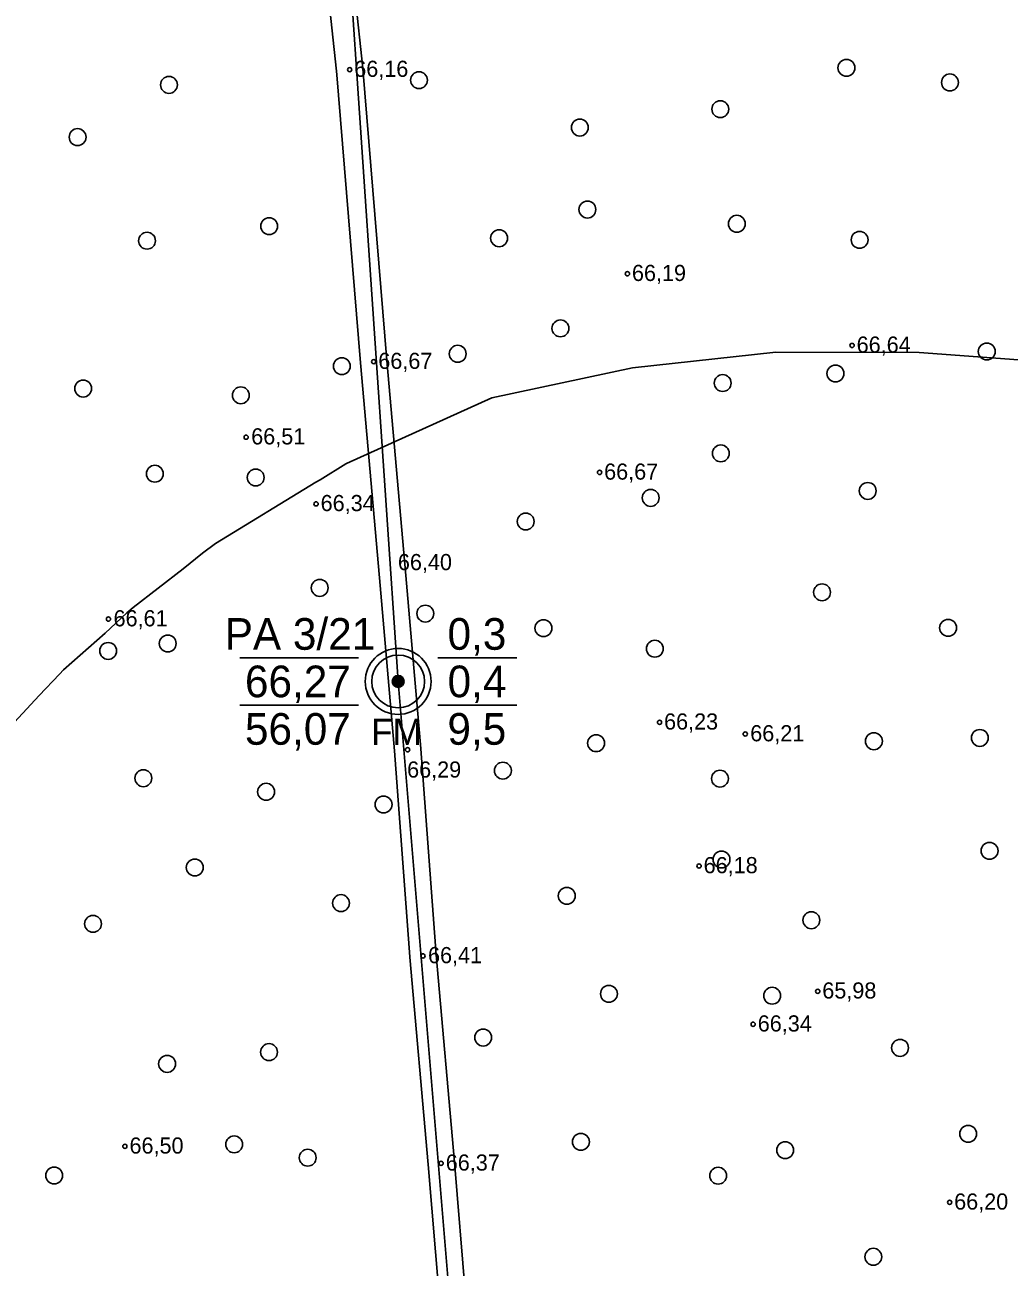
# Model space of a CAD drawing. Extents: x 532503 to 539665, y 6557663 to 6561526.
# Drawn here: x 534640.9 to 534790.2, y 6559799.2 to 6559987.5 of the extents above; entities that cross this region are included whole.
import ezdxf

# ---------------------------------------------------------------- set-up
doc = ezdxf.new("R2010")
doc.units = 0
for name, color, linetype in [('GEOLPUNKT', 7, 'Continuous'), ('HALJASTUS', 7, 'Continuous'), ('KORGUS-EH2000', 7, 'Continuous'), ('Lamami horisontaal_EH2000', 7, 'Continuous'), ('Lõige', 7, 'Continuous'), ('Proovid', 7, 'Continuous'), ('TEE', 7, 'Continuous')]:
    doc.layers.add(name, color=color, linetype=linetype)

# ---------------------------------------------------------------- blocks, each defined once
blk = doc.blocks.new('METS')
at = {"layer": 'HALJASTUS'}
blk.add_circle((0, 0), 0.8, dxfattribs=at)

msp = doc.modelspace()

# ---------------------------------------------------------------- linework, layer by layer
at = {"layer": 'GEOLPUNKT'}
for p, q in [((534673.52, 6559891.58), (534691.52, 6559891.58)), ((534703.52, 6559891.58), (534715.52, 6559891.58)), ((534673.52, 6559884.38), (534691.52, 6559884.38)), ((534703.52, 6559884.38), (534715.52, 6559884.38))]:
    msp.add_line(p, q, dxfattribs=at)
for radius in [5, 4, 0.9, 0.801, 0.7, 0.6, 0.5, 0.4, 0.3, 0.2, 0.1]:
    msp.add_circle((534697.52, 6559887.98), radius, dxfattribs=at)
at = {"layer": 'KORGUS-EH2000'}
for centre in [(534690.17, 6559980.74), (534732.29, 6559949.79), (534766.37, 6559938.92), (534693.81, 6559936.46), (534674.46, 6559925.01), (534728.07, 6559919.67), (534685.07, 6559914.9), (534653.58, 6559897.43), (534737.16, 6559881.78), (534750.16, 6559880), (534698.95, 6559877.62), (534743.16, 6559860), (534701.29, 6559846.36), (534761.16, 6559841), (534751.36, 6559836), (534656.07, 6559817.49), (534704.04, 6559814.91), (534781.16, 6559809)]:
    msp.add_circle(centre, 0.32, dxfattribs=at)
at = {"layer": 'Lamami horisontaal_EH2000'}
msp.add_lwpolyline([(534638.05, 6559880.42), (534643.05, 6559885.87), (534646.13, 6559889.1), (534646.78, 6559889.75), (534653.09, 6559895.32), (534656.36, 6559898.37), (534657.32, 6559899.2), (534664.9, 6559905.04), (534667.86, 6559907.45), (534669.84, 6559908.91), (534685.03, 6559918.18), (534685.67, 6559918.53), (534689.59, 6559920.99), (534689.7, 6559921.04), (534711.75, 6559930.99), (534733.06, 6559935.52), (534754.79, 6559937.88), (534776.53, 6559937.84), (534794.34, 6559936.54)], dxfattribs=at)
at = {"layer": 'Lõige'}
msp.add_lwpolyline([(534686.42, 6560054.5), (534688.17, 6560025.47), (534697.52, 6559887.98), (534707.91, 6559763.06), (534733.5, 6559485.14), (534735.54, 6559463.02)], dxfattribs=at)
at = {"layer": 'TEE'}
for p, q in [((534688.18, 6559980.53), (534685.22, 6560007.91)), ((534692.15, 6559980.96), (534689.2, 6560008.33)), ((534691.82, 6559936.29), (534688.17, 6559980.58)), ((534695.81, 6559936.62), (534692.16, 6559980.91)), ((534694.71, 6559903.7), (534691.82, 6559936.28)), ((534698.7, 6559904.05), (534695.81, 6559936.63)), ((534698.7, 6559904.04), (534700.94, 6559877.79)), ((534694.71, 6559903.7), (534696.95, 6559877.45)), ((534703.28, 6559846.51), (534700.94, 6559877.77)), ((534699.29, 6559846.21), (534696.95, 6559877.47)), ((534702.05, 6559814.74), (534699.29, 6559846.18)), ((534706.04, 6559815.09), (534703.28, 6559846.53)), ((534704.86, 6559781.73), (534702.05, 6559814.74)), ((534708.84, 6559782.07), (534706.04, 6559815.08))]:
    msp.add_line(p, q, dxfattribs=at)

# ---------------------------------------------------------------- block references
at = {"layer": 'HALJASTUS', "xscale": 1.6, "yscale": 1.6000000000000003}
for p in [(534765.51, 6559981.01), (534662.76, 6559978.42), (534700.68, 6559979.14), (534781.21, 6559978.8), (534746.38, 6559974.74), (534648.9, 6559970.51), (534725.07, 6559971.95), (534726.22, 6559959.52), (534748.89, 6559957.37), (534677.95, 6559957), (534659.43, 6559954.8), (534712.83, 6559955.17), (534767.51, 6559954.94), (534722.13, 6559941.51), (534706.55, 6559937.66), (534786.79, 6559938.01), (534688.97, 6559935.78), (534763.84, 6559934.66), (534746.74, 6559933.22), (534649.74, 6559932.38), (534673.65, 6559931.36), (534746.46, 6559922.56), (534660.62, 6559919.47), (534675.91, 6559918.9), (534768.74, 6559916.86), (534735.82, 6559915.8), (534716.86, 6559912.22), (534685.62, 6559902.16), (534761.81, 6559901.49), (534701.64, 6559898.26), (534719.55, 6559896.05), (534780.93, 6559896.1), (534662.57, 6559893.73), (534653.54, 6559892.6), (534736.45, 6559892.94), (534727.54, 6559878.61), (534769.68, 6559878.91), (534785.74, 6559879.41), (534713.41, 6559874.45), (534658.87, 6559873.3), (534746.33, 6559873.24), (534677.49, 6559871.25), (534695.31, 6559869.32), (534787.22, 6559862.29), (534666.67, 6559859.76), (534746.57, 6559860.98), (534688.85, 6559854.37), (534723.09, 6559855.47), (534760.19, 6559851.77), (534651.24, 6559851.22), (534729.49, 6559840.62), (534754.24, 6559840.33), (534710.41, 6559833.98), (534677.93, 6559831.78), (534773.64, 6559832.41), (534662.47, 6559829.99), (534725.24, 6559818.18), (534783.98, 6559819.38), (534672.65, 6559817.79), (534756.22, 6559816.91), (534683.8, 6559815.77), (534645.35, 6559813.07), (534746.05, 6559813.04), (534769.59, 6559800.75)]:
    msp.add_blockref('METS', p, dxfattribs=at)

# ---------------------------------------------------------------- texts
at = {"layer": 'GEOLPUNKT'}
for s, p in [('PA 3/21', (534671.21, 6559892.78)), ('0,3', (534705.01, 6559892.78)), ('66,27', (534674.28, 6559885.58)), ('0,4', (534705.02, 6559885.58)), ('56,07', (534674.28, 6559878.38)), ('9,5', (534704.99, 6559878.38))]:
    msp.add_text(s, height=4.8, dxfattribs=at).set_placement(p)
at = {"layer": 'KORGUS-EH2000'}
for s, p in [('66,16', (534690.86, 6559979.64)), ('66,19', (534732.98, 6559948.69)), ('66,64', (534767.06, 6559937.82)), ('66,67', (534694.51, 6559935.36)), ('66,51', (534675.23, 6559923.91)), ('66,67', (534728.76, 6559918.57)), ('66,34', (534685.76, 6559913.8)), ('66,40', (534697.48, 6559904.85)), ('66,61', (534654.35, 6559896.33)), ('66,23', (534737.85, 6559880.68)), ('66,21', (534750.92, 6559878.9)), ('66,29', (534698.88, 6559873.4)), ('66,18', (534743.85, 6559858.9)), ('66,41', (534702.05, 6559845.26)), ('65,98', (534761.85, 6559839.9)), ('66,34', (534752.06, 6559834.9)), ('66,50', (534656.77, 6559816.39)), ('66,37', (534704.74, 6559813.81)), ('66,20', (534781.85, 6559807.9))]:
    msp.add_text(s, height=2.45, dxfattribs=at).set_placement(p)
at = {"layer": 'Proovid'}
msp.add_text('FM', height=4, dxfattribs=at).set_placement((534693.4, 6559878.34))

doc.saveas('drawing.dxf')
